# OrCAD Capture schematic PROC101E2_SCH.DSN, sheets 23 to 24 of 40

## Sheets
23 26.FT4232 UART TO USB BRIDGE: size C; title: FT4232 UART TO USB BRIDGE
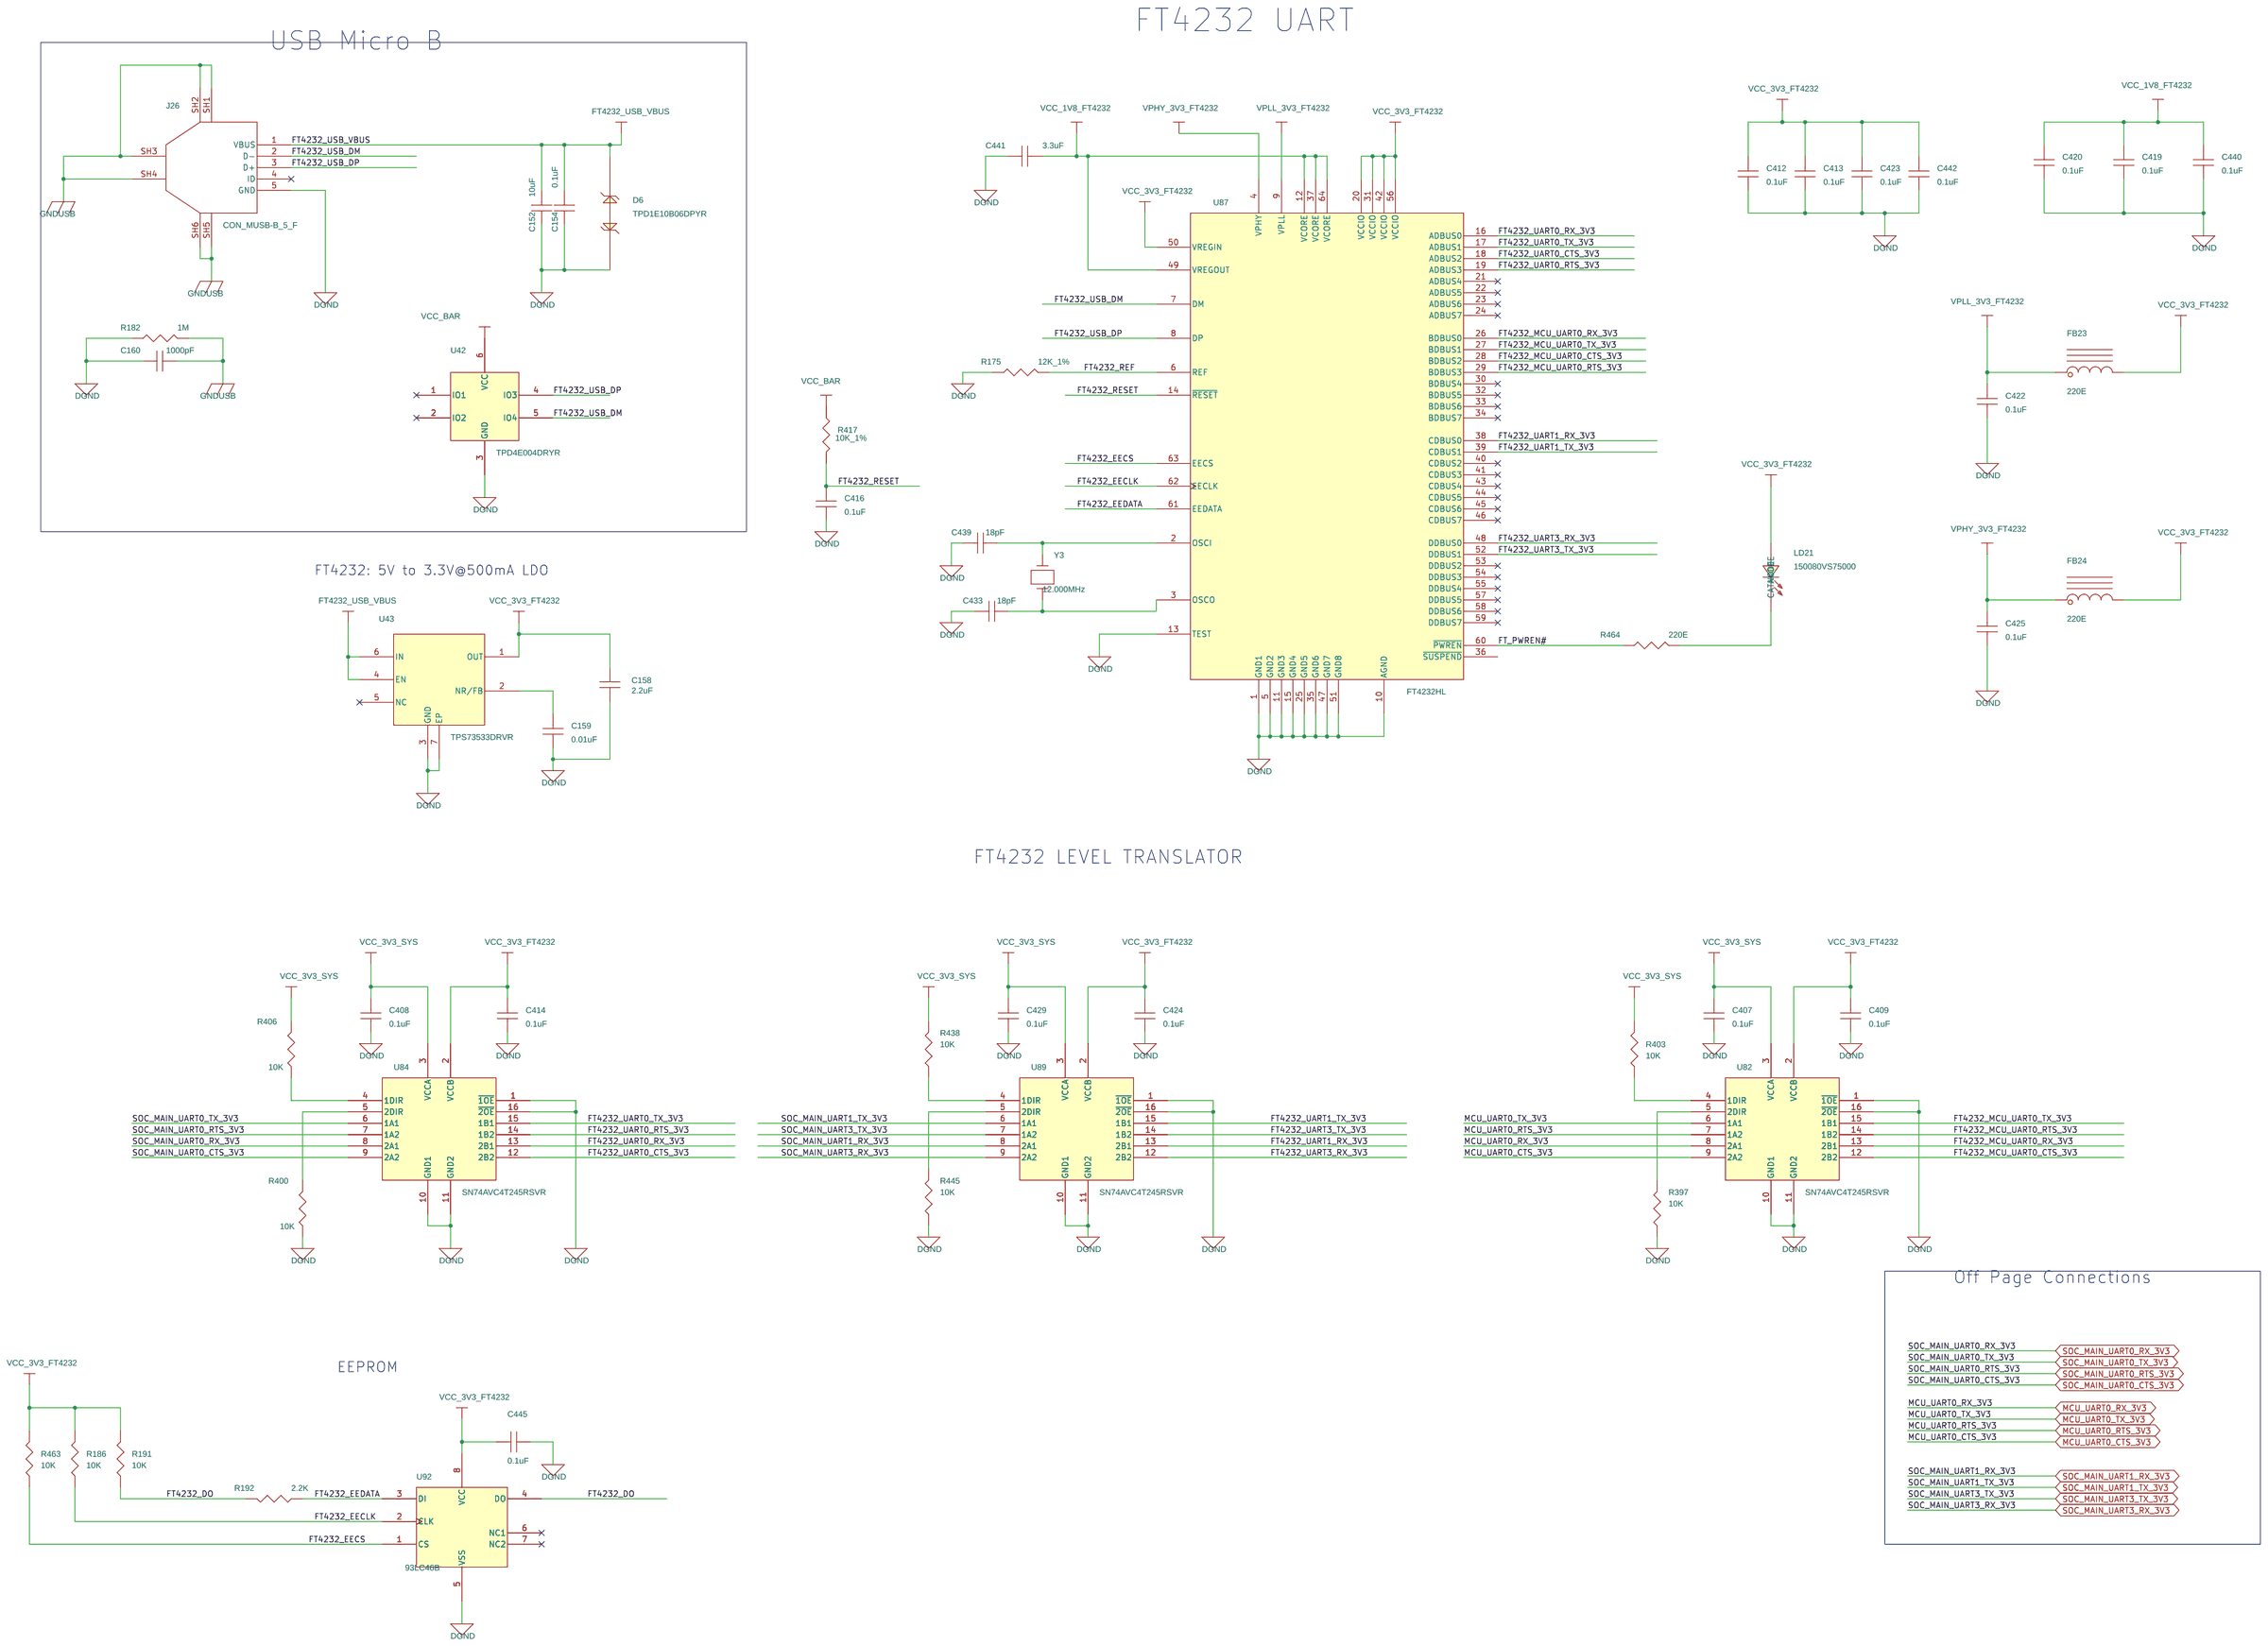
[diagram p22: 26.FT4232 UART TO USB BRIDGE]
24 13.eMMC & SD CARD INTERFACE: size C; title: eMMC FLASH_SDCARD INTERFACE
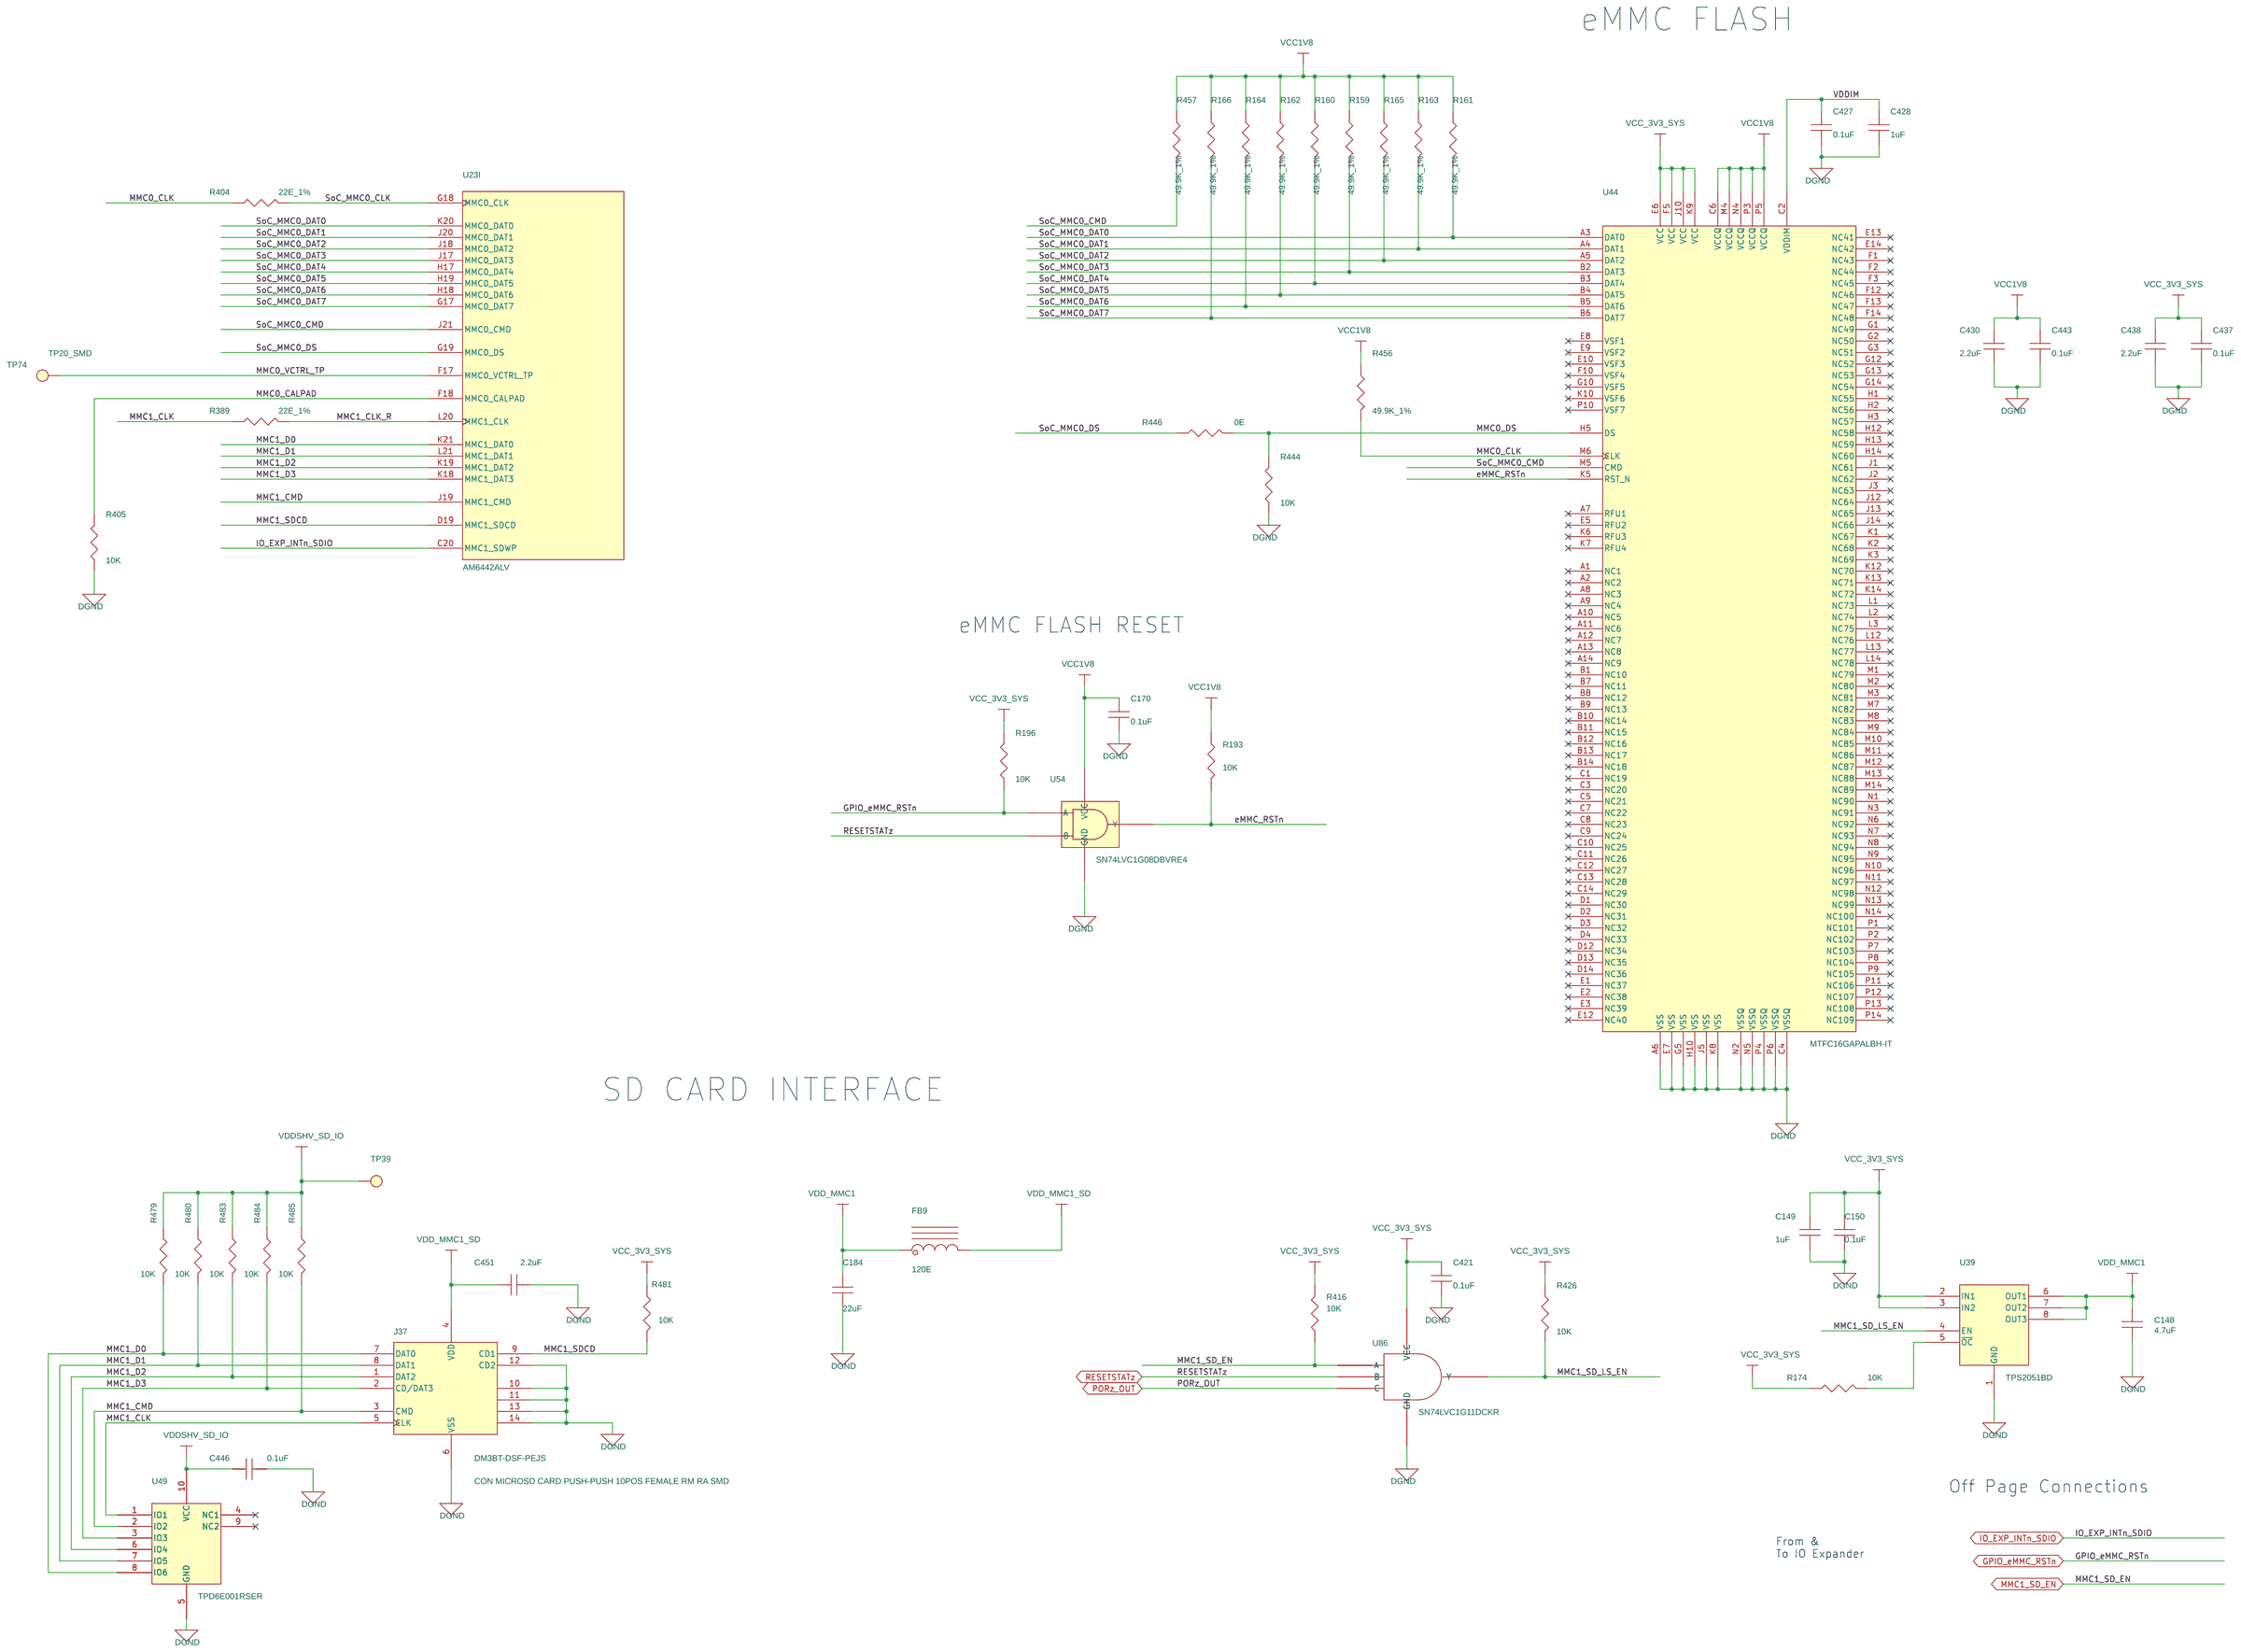
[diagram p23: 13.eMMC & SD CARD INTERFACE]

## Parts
sheet 11.SOC VSS
U23  AM6442ALV  [FCBGA441_31-49_680X680_2-6]  (sections A,B,C,D,E,F,G,H,I,J,K,L,M,N,O,P)
sheet 13.eMMC & SD CARD INTERFACE
C148  4.7uF  [CAP0402_0-75]
C149  1uF  [CAP0402_0-75]
C150  0.1uF  [CAP0402_0-75]
C170  0.1uF  [CAP0402_0-75]
C184  22uF  [CAP0805_1-5]
C421  0.1uF  [CAP0402_0-75]
C427  0.1uF  [CAP0402_0-75]
C428  1uF  [CAP0402_0-75]
C430  2.2uF  [CAP0402_0-75]
C437  0.1uF  [CAP0402_0-75]
C438  2.2uF  [CAP0402_0-75]
C443  0.1uF  [CAP0402_0-75]
C446  0.1uF  [CAP0402_0-75]
C451  2.2uF  [CAP0402_0-75]
FB9  120E  [IND0603_1]
J37  CON_SDCARD10_DM3BT-DSF-PEJS  [CON_SD10_DM3BT-DSF-PEJS_S_R_S_2-4]
R159  49.9K_1%  [RES0402_0-5]
R160  49.9K_1%  [RES0402_0-5]
R161  49.9K_1%  [RES0402_0-5]
R162  49.9K_1%  [RES0402_0-5]
R163  49.9K_1%  [RES0402_0-5]
R164  49.9K_1%  [RES0402_0-5]
R165  49.9K_1%  [RES0402_0-5]
R166  49.9K_1%  [RES0402_0-5]
R174  10K  [RES0402_0-5]
R193  10K  [RES0402_0-5]
R196  10K  [RES0402_0-5]
R389  22E_1%  [RES0402_0-5]
R404  22E_1%  [RES0402_0-5]
R405  10K  [RES0402_0-5]
R416  10K  [RES0402_0-5]
R426  10K  [RES0402_0-5]
R444  10K  [RES0402_0-5]
R446  0E  [RES0402_0-5]
R456  49.9K_1%  [RES0402_0-5]
R457  49.9K_1%  [RES0402_0-5]
R479  10K  [RES0402_0-5]
R480  10K  [RES0402_0-5]
R481  10K  [RES0402_0-5]
R483  10K  [RES0402_0-5]
R484  10K  [RES0402_0-5]
R485  10K  [RES0402_0-5]
TP39  TP20_SMD  [TP20_SMD]
TP74  TP20_SMD  [TP20_SMD]
U39  TPS2051BD  [SOIC8_1-8]
U44  MTFC16GAPALBH-IT  [VFBGA153_19-68_460X520_1-1]
U49  TPD6E001RSER  [UQFN10_19-68_80X60_0-6]
U54  SN74LVC1G08DBVRE4  [SOT23-5]
U86  SN74LVC1G11DCKR  [SC70-6]
sheet 26.FT4232 UART TO USB BRIDGE
C152  10uF  [CAP0402_0-75]
C154  0.1uF  [CAP0402_0-75]
C158  2.2uF  [CAP0402_0-75]
C159  0.01uF  [CAP0402_0-75]
C160  1000pF  [CAP1206_1-75]
C407  0.1uF  [CAP0402_0-75]
C408  0.1uF  [CAP0402_0-75]
C409  0.1uF  [CAP0402_0-75]
C412  0.1uF  [CAP0402_0-75]
C413  0.1uF  [CAP0402_0-75]
C414  0.1uF  [CAP0402_0-75]
C416  0.1uF  [CAP0402_0-75]
C419  0.1uF  [CAP0402_0-75]
C420  0.1uF  [CAP0402_0-75]
C422  0.1uF  [CAP0402_0-75]
C423  0.1uF  [CAP0402_0-75]
C424  0.1uF  [CAP0402_0-75]
C425  0.1uF  [CAP0402_0-75]
C429  0.1uF  [CAP0402_0-75]
C433  18pF  [CAP0402_0-75]
C439  18pF  [CAP0402_0-75]
C440  0.1uF  [CAP0402_0-75]
C441  3.3uF  [CAP0402_0-75]
C442  0.1uF  [CAP0402_0-75]
C445  0.1uF  [CAP0402_0-75]
D6  TPD1E10B06DPYR  [DIO_DFN0402_0-5]
FB23  220E  [IND0402_0-6]
FB24  220E  [IND0402_0-6]
J26  CON_MUSB-B_5_F  [CON_MUSBB5_1051640001_S_R_S_2-5]
LD21  150080VS75000  [LED_150080VS75000_80X50_SMD_0-8]
R175  12K_1%  [RES0402_0-5]
R182  1M  [RES0603_0-75]
R186  10K  [RES0402_0-5]
R191  10K  [RES0402_0-5]
R192  2.2K  [RES0402_0-5]
R397  10K  [RES0402_0-5]
R400  10K  [RES0402_0-5]
R403  10K  [RES0402_0-5]
R406  10K  [RES0402_0-5]
R417  10K_1%  [RES0402_0-5]
R438  10K  [RES0402_0-5]
R445  10K  [RES0402_0-5]
R463  10K  [RES0402_0-5]
R464  220E  [RES0402_0-5]
U42  TPD4E004DRYR  [SON6_19-68_40X60_PB_0-6]
U43  TPS73533DRVR  [SON6_25-59_85X85]
U82  SN74AVC4T245RSVR  [UQFN16_TMUX1574_70X100_0-6]
U84  SN74AVC4T245RSVR  [UQFN16_TMUX1574_70X100_0-6]
U87  FT4232HL  [LQFP64_19-68_390X390_1-6]
U89  SN74AVC4T245RSVR  [UQFN16_TMUX1574_70X100_0-6]
U92  93LC46B  [MSOP8_25-59_125X125_1-1]
Y3  12.000MHz  [XTAL_ABM3_205X130_SMD_1-4]

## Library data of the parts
U23 = AM64-SVB_BGA441: IC AM64 SoC MICROPROCESSOR BGA441; Chkd/date: MANIRAJA/020520; Crtd /date: ALVY/090420; Custom_Duty: 15%; Customs_HS_Code: 85423100; Distributor_name: NA; Distributor_part_number: NA; Footprint Path: Y:\MIS_DATABASE\Library\ALTIUM_TOOL\PCB_FOOTPRINTS\Altium_Footprint_Lib.PcbLib; Height: 2.57MM; Library Path: Y:\MIS_DATABASE\Library\ALTIUM_TOOL\SCHEMATICS_PARTS\MS_MICROPROCESSOR_Library.schlib; Mfr_name: TEXAS INSTRUMENTS; Mfr_part_number: AM6442ASFGGAALV; Mistral Part No: 141220040002; Package: BGA441; Part_type: ICS\DIGITAL\MICROPROCESSOR; Project: AM64x_SVB BRD; RoHS: NA; Temperature: NA; Tolerance: NA; Voltage: NA; Wattage: NA; Weight: NA; Datasheet: Y:\MIS_DATABASE\DATASHEETS\ICS\DIGITAL\MICROCONTROLLER\AM64-SoC_SVB.PDF
C148 = CAP: CAP CERAMIC 4.7uF 10V 20% X5R 0402; Chkd/date: MANIRAJA/230118; Crtd /date: MANIRAJA/230118; Custom_Duty: 15%; Customs_HS_Code: 85322990; Distributor_name: DIGIKEY; Distributor_part_number: 478-10791-1-ND; Footprint Path: Y:\MIS_DATABASE\Library\ALTIUM_TOOL\PCB_FOOTPRINTS\Altium_Footprint_Lib.PcbLib; Height: 0.71MM; Library Path: Y:\MIS_DATABASE\Library\ALTIUM_TOOL\SCHEMATICS_PARTS\MS_DISCRETE_Library.schlib; Mfr_name: AVX CORPORATION; Mfr_part_number: 0402ZD475MAT2A; Mistral Part No: 120012060002-R; Package: 0402; Part_type: CAPACITORS\CERAMIC; Project: TI_MAXIE_CPB; RoHS: RoHS; Temperature: -55°C+85°C; Tolerance: 20%; Voltage: 10V; Wattage: NA; Weight: 0.65mg; Datasheet: Y:\MIS_DATABASE\DATASHEETS\CAPACITORS\AVX_MLC.PDF
C149 C428 = CAP: CAP CERAMIC 1uF 10V 20% X5R 0402; Chkd/date: MANIRAJA/210820; Crtd /date: ALVY/190820; Custom_Duty: 15%; Customs_HS_Code: 85322990; Distributor_name: DIGIKEY; Distributor_part_number: 732-7489-1-ND; Footprint Path: Y:\MIS_DATABASE\Library\ALTIUM_TOOL\PCB_FOOTPRINTS\Altium_Footprint_Lib.PcbLib; Height: 0.55MM; Library Path: Y:\MIS_DATABASE\Library\ALTIUM_TOOL\SCHEMATICS_PARTS\MS_DISCRETE_Library.schlib; Mfr_name: WURTH ELECTRONICS; Mfr_part_number: 885012105012; Mistral Part No: 120020080009-R; Package: 0402; Part_type: CAPACITORS\CERAMIC; Project: AM64x_EVM_BRD; RoHS: RoHS; Temperature: -55°C+85°C; Tolerance: 20%; Voltage: 10V; Wattage: NA; Weight: 0.65mg; Datasheet: Y:\MIS_DATABASE\DATASHEETS\CAPACITORS\885012105012.PDF
C150 C154 C170 C407-C409 C412-C414 C416 C419-C425 C427 C429 C437 C440 C442 C443 C445 C446 = CAP: CAP CERAMIC 0.1uF 25V 20% X5R 0402; Alt_Mfr_name: YAGEO AMERICA; Alt_Mfr_part_number: CC0402KRX5R8BB104; Chkd/date: MANIRAJA/170820; Crtd /date: ALVY/170820; Custom_Duty: 15%; Customs_HS_Code: 85322990; Distributor_name: DIGIKEY; Distributor_part_number: 732-7495-1-ND; Footprint Path: Y:\MIS_DATABASE\Library\ALTIUM_TOOL\PCB_FOOTPRINTS\Altium_Footprint_Lib.PcbLib; Height: 0.55MM; Library Path: Y:\MIS_DATABASE\Library\ALTIUM_TOOL\SCHEMATICS_PARTS\MS_DISCRETE_Library.schlib; Mfr_name: WURTH ELECTRONICS; Mfr_part_number: 885012105018; Mistral Part No: 120020080003-R; Package: 0402; Part_type: CAPACITORS\CERAMIC; Project: AM64x_EVM_BRD; RoHS: RoHS; Temperature: -55°C+85°C; Tolerance: 20%; Voltage: 25V; Wattage: NA; Weight: 0.65mg; Datasheet: Y:\MIS_DATABASE\DATASHEETS\CAPACITORS\885012105018.PDF
C184 = CAP: CAP CERAMIC 22uF 10V 20% X5R 0805; Chkd/date: MANIRAJA/210820; Crtd /date: ALVY/190820; Custom_Duty: 15%; Customs_HS_Code: 85322990; Distributor_name: DIGIKEY; Distributor_part_number: 732-7621-1-ND; Footprint Path: Y:\MIS_DATABASE\Library\ALTIUM_TOOL\PCB_FOOTPRINTS\Altium_Footprint_Lib.PcbLib; Height: 1.45MM; Library Path: Y:\MIS_DATABASE\Library\ALTIUM_TOOL\SCHEMATICS_PARTS\MS_DISCRETE_Library.schlib; Mfr_name: WURTH ELECTRONICS; Mfr_part_number: 885012107011; Mistral Part No: 120020080010-R; Package: 0805; Part_type: CAPACITORS\CERAMIC; Project: AM64x_EVM_BRD; RoHS: RoHS; Temperature: -55°C+85°C; Tolerance: 20%; Voltage: 10V; Wattage: NA; Weight: 5.5mg; Datasheet: Y:\MIS_DATABASE\DATASHEETS\CAPACITORS\885012107011.PDF
C158 C430 C438 C451 = CAP: CAP CERAMIC 2.2uF 10V 20% X5R 0402; Chkd/date: MANIRAJA/170820; Crtd /date: ALVY/170820; Custom_Duty: 15%; Customs_HS_Code: 85322990; Distributor_name: DIGIKEY; Distributor_part_number: 732-7490-1-ND; Footprint Path: Y:\MIS_DATABASE\Library\ALTIUM_TOOL\PCB_FOOTPRINTS\Altium_Footprint_Lib.PcbLib; Height: 0.55MM; Library Path: Y:\MIS_DATABASE\Library\ALTIUM_TOOL\SCHEMATICS_PARTS\MS_DISCRETE_Library.schlib; Mfr_name: WURTH ELECTRONICS; Mfr_part_number: 885012105013; Mistral Part No: 120019040036-R; Package: 0402; Part_type: CAPACITORS\CERAMIC; Project: AM64x_EVM_BRD; RoHS: RoHS; Temperature: -55°C+85°C; Tolerance: 20%; Voltage: 10V; Wattage: NA; Weight: 0.65mg; Datasheet: Y:\MIS_DATABASE\DATASHEETS\CAPACITORS\885012105013.PDF
FB9 = INDUCTOR_FERRITE: IND FERRITE BEAD CHIP 120E 2A 0603; Chkd/date: MANIRAJA/180820; Crtd /date: ALVY/180820; Custom_Duty: 24%; Customs_HS_Code: 85437099; Distributor_name: DIGIKEY; Distributor_part_number: 732-782631141CT-ND; Footprint Path: Y:\MIS_DATABASE\Library\ALTIUM_TOOL\PCB_FOOTPRINTS\Altium_Footprint_Lib.PcbLib; Height: 1.00MM; Library Path: Y:\MIS_DATABASE\Library\ALTIUM_TOOL\SCHEMATICS_PARTS\MS_FILTER_Library.schlib; Mfr_name: WURTH ELECTRONICS; Mfr_part_number: 782631141; Mistral Part No: 130020080015-R; Package: 0603; Part_type: INDUCTOR; Project: AM64x_EVM_BRD; RoHS: RoHS; Temperature: -55°C+125°C; Tolerance: 25%; Voltage: NA; Wattage: NA; Weight: NA; Datasheet: Y:\MIS_DATABASE\DATASHEETS\DISCRETES\INDUCTORS\782631141.PDF
J37 = CON_SDCARD_10_DM3BT-DSF-PEJS: CON MICROSD CARD PUSH-PUSH 10POS FEMALE RM RA SMD; Chkd/date: MANIRAJA/080218; Crtd /date: BAVISH/190111; Custom_Duty: 24%; Customs_HS_Code: 85369090; Distributor_name: DIGIKEY; Distributor_part_number: HR1942CT-ND; Footprint Path: Y:\MIS_DATABASE\Library\ALTIUM_TOOL\PCB_FOOTPRINTS\Altium_Footprint_Lib.PcbLib; Height: 2.38MM; Library Path: Y:\MIS_DATABASE\Library\ALTIUM_TOOL\SCHEMATICS_PARTS\MS_CONNECTOR_Library.schlib; Mfr_name: HIROSE ELECTRIC; Mfr_part_number: DM3BT-DSF-PEJS; Mistral Part No: 150011010020-R; Package: SMD; Part_type: CONNECTOR\MEMORY CARD; Project: EBOOK; RoHS: RoHS; Temperature: -25°C+85°C; Tolerance: NA; Voltage: NA; Wattage: NA; Weight: 1.315g; Datasheet: Y:\MIS_DATABASE\DATASHEETS\CONNECTORS\DM3-SERIES.PDF
R159-R166 R457 = RESISTOR: RES 49.9K 1/16W 1% 0402; Assembly: DNI; Chkd/date: MAZHAR/220709; Crtd /date: GEETHA/090606; Custom_Duty: 15%; Customs_HS_Code: 85332119; Distributor_name: DIGIKEY; Distributor_part_number: 311-49.9KLRCT-ND; Footprint Path: Y:\MIS_DATABASE\Library\ALTIUM_TOOL\PCB_FOOTPRINTS\Altium_Footprint_Lib.PcbLib; Height: 0.40MM; Library Path: Y:\MIS_DATABASE\Library\ALTIUM_TOOL\SCHEMATICS_PARTS\MS_DISCRETE_Library.schlib; Mfr_name: YAGEO AMERICA; Mfr_part_number: RC0402FR-0749K9L; Mistral Part No: 110009030902-R; Package: 0402; Part_type: RESISTORS\FIXED; Project: PNAV; RoHS: RoHS; Temperature: -55°C+155°C; Tolerance: 1%; Voltage: NA; Wattage: 1/16W; Weight: 0.65mg; Datasheet: Y:\MIS_DATABASE\DATASHEETS\RESISTORS\RCXXXXL-SER_MAR18.PDF
R174 R186 R191 R196 R397 R400 R403 R405 R406 R416 R438 R444 R445 R463 R481 = RESISTOR: RES 10K 1/16W 5% 0402; Chkd/date: VASANTHA/061216; Crtd /date: MAZHAR/230805; Custom_Duty: 15%; Customs_HS_Code: 85332119; Distributor_name: DIGIKEY; Distributor_part_number: 311-10KJRCT-ND; Footprint Path: Y:\MIS_DATABASE\Library\ALTIUM_TOOL\PCB_FOOTPRINTS\Altium_Footprint_Lib.PcbLib; Height: 0.40MM; Library Path: Y:\MIS_DATABASE\Library\ALTIUM_TOOL\SCHEMATICS_PARTS\MS_DISCRETE_Library.schlib; Mfr_name: YAGEO AMERICA; Mfr_part_number: RC0402JR-0710KL; Mistral Part No: 110011060021-R; Package: 0402; Part_type: RESISTORS\FIXED; Project: HSE; RoHS: RoHS; Temperature: -55°C+155°C; Tolerance: 5%; Voltage: NA; Wattage: 1/16W; Weight: 0.65mg; Datasheet: Y:\MIS_DATABASE\DATASHEETS\RESISTORS\RCXXXXL-SER_MAR18.PDF
R193 R426 R479 R480 R483-R485 = RESISTOR: RES 10K 1/16W 5% 0402; Assembly: DNI; Chkd/date: VASANTHA/061216; Crtd /date: MAZHAR/230805; Custom_Duty: 15%; Customs_HS_Code: 85332119; Distributor_name: DIGIKEY; Distributor_part_number: 311-10KJRCT-ND; Footprint Path: Y:\MIS_DATABASE\Library\ALTIUM_TOOL\PCB_FOOTPRINTS\Altium_Footprint_Lib.PcbLib; Height: 0.40MM; Library Path: Y:\MIS_DATABASE\Library\ALTIUM_TOOL\SCHEMATICS_PARTS\MS_DISCRETE_Library.schlib; Mfr_name: YAGEO AMERICA; Mfr_part_number: RC0402JR-0710KL; Mistral Part No: 110011060021-R; Package: 0402; Part_type: RESISTORS\FIXED; Project: HSE; RoHS: RoHS; Temperature: -55°C+155°C; Tolerance: 5%; Voltage: NA; Wattage: 1/16W; Weight: 0.65mg; Datasheet: Y:\MIS_DATABASE\DATASHEETS\RESISTORS\RCXXXXL-SER_MAR18.PDF
R389 = RESISTOR: RES 22E 1/16W 1% 0402; Chkd/date: SUHAS/290910; Crtd /date: MAZHAR/090909; Cust_part_number: 4700-80047E; Custom_Duty: 15%; Customs_HS_Code: 85332119; Distributor_name: DIGIKEY; Distributor_part_number: 311-22.0LRCT-ND; Footprint Path: Y:\MIS_DATABASE\Library\ALTIUM_TOOL\PCB_FOOTPRINTS\Altium_Footprint_Lib.PcbLib; Height: 0.40MM; Library Path: Y:\MIS_DATABASE\Library\ALTIUM_TOOL\SCHEMATICS_PARTS\MS_DISCRETE_Library.schlib; Mfr_name: YAGEO AMERICA; Mfr_part_number: RC0402FR-0722RL; Mistral Part No: 110009090004-R; Package: 0402; Part_type: RESISTORS\FIXED; Project: VMEFMCD; RoHS: RoHS; Temperature: -55°C+155°C; Tolerance: 1%; Voltage: NA; Wattage: 1/16W; Weight: 0.65mg; Datasheet: Y:\MIS_DATABASE\DATASHEETS\RESISTORS\RCXXXXL-SER_MAR18.PDF
R404 = RESISTOR: RES 22E 1/16W 1% 0402; Chkd/date: SUHAS/290910; Crtd /date: MAZHAR/090909; Cust_part_number: 4700-80047E; Custom_Duty: 15%; Customs_HS_Code: 85332119; Distributor_name: DIGIKEY; Distributor_part_number: 311-22.0LRCT-ND; Footprint Path: Y:\MIS_DATABASE\Library\ALTIUM_TOOL\PCB_FOOTPRINTS\Altium_Footprint_Lib.PcbLib; Height: 0.40MM; Library Path: Y:\MIS_DATABASE\Library\ALTIUM_TOOL\SCHEMATICS_PARTS\MS_DISCRETE_Library.schlib; Mfr_name: YAGEO AMERICA; Mfr_part_number: RC0402FR-0722RL; Mistral Part No: 110009090004-R; Package: 0402; Part_type: RESISTORS\FIXED; Project: VMEFMCD; RoHS: RoHS; SIGNAL_MODEL: RESISTOR_RES0402_22E_22E; Temperature: -55°C+155°C; Tolerance: 1%; Voltage: NA; Wattage: 1/16W; Weight: 0.65mg; Datasheet: Y:\MIS_DATABASE\DATASHEETS\RESISTORS\RCXXXXL-SER_MAR18.PDF
R446 = RESISTOR: RES 0E 1/16W JUMPER 0402; Chkd/date: VASANTHA/201216; Crtd /date: MUDDU/190810; Custom_Duty: 15%; Customs_HS_Code: 85332119; Distributor_name: DIGIKEY; Distributor_part_number: 541-0.0JCT-ND; Footprint Path: Y:\MIS_DATABASE\Library\ALTIUM_TOOL\PCB_FOOTPRINTS\Altium_Footprint_Lib.PcbLib; Height: 0.40MM; Library Path: Y:\MIS_DATABASE\Library\ALTIUM_TOOL\SCHEMATICS_PARTS\MS_DISCRETE_Library.schlib; Mfr_name: VISHAY; Mfr_part_number: CRCW04020000Z0ED; Mistral Part No: 110010080019-R; Package: 0402; Part_type: RESISTORS\FIXED; Project: PB_BUGBASE; RoHS: RoHS; Temperature: -55°C+155°C; Tolerance: NA; Voltage: NA; Wattage: 1/16W; Weight: 0.65mg; Datasheet: Y:\MIS_DATABASE\DATASHEETS\RESISTORS\CRCW0603.PDF
R456 = RESISTOR: RES 49.9K 1/16W 1% 0402; Chkd/date: MAZHAR/220709; Crtd /date: GEETHA/090606; Custom_Duty: 15%; Customs_HS_Code: 85332119; Distributor_name: DIGIKEY; Distributor_part_number: 311-49.9KLRCT-ND; Footprint Path: Y:\MIS_DATABASE\Library\ALTIUM_TOOL\PCB_FOOTPRINTS\Altium_Footprint_Lib.PcbLib; Height: 0.40MM; Library Path: Y:\MIS_DATABASE\Library\ALTIUM_TOOL\SCHEMATICS_PARTS\MS_DISCRETE_Library.schlib; Mfr_name: YAGEO AMERICA; Mfr_part_number: RC0402FR-0749K9L; Mistral Part No: 110009030902-R; Package: 0402; Part_type: RESISTORS\FIXED; Project: PNAV; RoHS: RoHS; Temperature: -55°C+155°C; Tolerance: 1%; Voltage: NA; Wattage: 1/16W; Weight: 0.65mg; Datasheet: Y:\MIS_DATABASE\DATASHEETS\RESISTORS\RCXXXXL-SER_MAR18.PDF
TP39 TP74 = TESTPOINT: TESTPOINT CIR 20 SMD; Chkd/date: SHREESHAIL/171006; Crtd /date: MAZHAR/171006; Custom_Duty: NA; Customs_HS_Code: NA; Distributor_name: NA; Distributor_part_number: NA; Footprint Path: Y:\MIS_DATABASE\Library\ALTIUM_TOOL\PCB_FOOTPRINTS\Altium_Footprint_Lib.PcbLib; Height: NA; Library Path: Y:\MIS_DATABASE\Library\ALTIUM_TOOL\SCHEMATICS_PARTS\MS_DISCRETE_Library.schlib; MECHANICAL 3D STEP FILE: NA; Mfr_name: LOCAL; Mistral Part No: NA; Package: SMD; Project: BT MODULE_CSRBC04; RoHS: NA; Temperature: NA; Tolerance: NA; Voltage: NA; Wattage: NA; Weight: NA; Datasheet: NA
U39 = TPS2051BD_SOIC8: IC POWER DISTRIBUTION SWITCH SOIC8; Chkd/date: NAVEED/150714; Crtd /date: VASANTHA/190614; Custom_Duty: 15%; Customs_HS_Code: 85423100; Distributor_name: DIGIKEY; Distributor_part_number: 296-26911-5-ND; Footprint Path: Y:\MIS_DATABASE\Library\ALTIUM_TOOL\PCB_FOOTPRINTS\Altium_Footprint_Lib.PcbLib; Height: 1.75MM; Library Path: Y:\MIS_DATABASE\Library\ALTIUM_TOOL\SCHEMATICS_PARTS\MS_MISCPOWER_Library.schlib; Mfr_name: TEXAS INSTRUMENTS; Mistral Part No: 142014060011-R; Package: SOIC8; Part_type: ICS\POWER; Project: AEGIS_POM; RoHS: RoHS; Temperature: -40°C+125°C; Tolerance: NA; Voltage: NA; Wattage: NA; Weight: 72.6mg; Datasheet: Y:\MIS_DATABASE\DATASHEETS\MISC\REGULATORS\TPS2051BDBVR.PDF
U44 = MTFC16GAPALBH_TFBGA153: IC 16GB e-MMC MEMORY TFBGA153; Chkd/date: MANIRAJA/070220; Crtd /date: ALVY/070220; Custom_Duty: 15%; Customs_HS_Code: 85423100; Distributor_name: DIGIKEY; Distributor_part_number: MTFC16GAPALBH-IT-ND; Footprint Path: Y:\MIS_DATABASE\Library\ALTIUM_TOOL\PCB_FOOTPRINTS\Altium_Footprint_Lib.PcbLib; Height: 1.10MM; Library Path: Y:\MIS_DATABASE\Library\ALTIUM_TOOL\SCHEMATICS_PARTS\MS_MISCMEMORY_Library.schlib; Mfr_name: MICRON; Mistral Part No: 141120020001-R; Package: TFBGA153; Part_type: ICS\DIGITAL\MEMORY; Project: TI_MAXIE_CPB; RoHS: RoHS; Temperature: -40°C+85°C; Tolerance: NA; Voltage: NA; Wattage: NA; Weight: NA; Datasheet: Y:\MIS_DATABASE\DATASHEETS\ICS\MEMORY\MTFCXX-IT.PDF
U49 = TPD6E001RSE_UQFN10: IC 6CH ESD-PROTECTION ARRAY UQFN10; Chkd/date: USMAN/070612; Crtd /date: BAVISH/160811; Custom_Duty: 15%; Customs_HS_Code: 85423100; Distributor_name: DIGIKEY; Distributor_part_number: 296-21888-1-ND; Footprint Path: Y:\MIS_DATABASE\Library\ALTIUM_TOOL\PCB_FOOTPRINTS\Altium_Footprint_Lib.PcbLib; Height: 0.60MM; IBISSP_MODLES: Y:\MIS_DATABASE\IBIS\ICs\INTERFACE\TPD6E001RSE.IBS; Library Path: Y:\MIS_DATABASE\Library\ALTIUM_TOOL\SCHEMATICS_PARTS\MS_MISCINTERFACE_Library.schlib; Mfr_name: TEXAS INSTRUMENTS; Mistral Part No: 141011080020-R; Package: UQFN10; Part_type: ICS\INTERFACE; Project: DM385EVM_BASE-BOARD; RoHS: RoHS; Temperature: -40°C+85°C; Tolerance: NA; Voltage: NA; Wattage: NA; Weight: 7mg; Datasheet: Y:\MIS_DATABASE\DATASHEETS\ICS\INTERFACE\TPD6E001.PDF
U54 = SN74LVC1G08DBVRE4_SOT23-5: IC SINGLE 2-INPUT POSITIVE AND GATE SOT23-5; Chkd/date: SUHAS/221010; Crtd /date: USMAN/151008; Custom_Duty: 15%; Customs_HS_Code: 85423100; Distributor_name: DIGIKEY; Distributor_part_number: SN74LVC1G08DBVRE4-ND; Height: 1.45MM; Mfr_name: TEXAS INSTRUMENTS; Mistral Part No: 141009060026-R; Part_type: ICS\DIGITAL\GATES; Project: KHAN_MAIN; RoHS: Sb/ Br FREE; Temperature: -40°C+85°C; Datasheet: Y:\MIS_DATABASE\DATASHEETS\ICS\DIGITAL\GATES\SN74LVC1G08.PDF
U86 = SN74LVC1G11DCKR_SC70-6: IC SINGLE 3-INPUT POSITIVE-AND GATE SC70-6; Chkd/date: SHREESHAIL/220506; Crtd /date: MAZHAR/150506; Custom_Duty: 15%; Customs_HS_Code: 85423100; Distributor_name: DIGIKEY; Distributor_part_number: 296-18066-1-ND; Height: 1.10MM; Mfr_name: TEXAS INSTRUMENTS; Mistral Part No: 141009030230-R; Part_type: ICS\DIGITAL\GATES; Project: VOCERA; RoHS: Sb/ Br FREE; Datasheet: Y:\MIS_DATABASE\DATASHEETS\ICS\DIGITAL\GATES\SN74LVC1G.PDF
C152 = CAP: CAP CERAMIC 10uF 10V 20% X5R 0402; Chkd/date: MANIRAJA/300520; Crtd /date: ALVY/260520; Custom_Duty: 15%; Customs_HS_Code: 85322990; Distributor_name: DIGIKEY; Distributor_part_number: 490-GRM155R61A106ME11DTR-ND; Footprint Path: Y:\MIS_DATABASE\Library\ALTIUM_TOOL\PCB_FOOTPRINTS\Altium_Footprint_Lib.PcbLib; Height: 0.55MM; Library Path: Y:\MIS_DATABASE\Library\ALTIUM_TOOL\SCHEMATICS_PARTS\MS_DISCRETE_Library.schlib; Mfr_name: MURATA; Mfr_part_number: GRM155R61A106ME11D; Mistral Part No: 120013110019-R; Package: 0402; Part_type: CAPACITORS\CERAMIC; Project: QCS610_NANOSOM; RoHS: RoHS; Temperature: -55°C+85°C; Tolerance: 20%; Voltage: 10V; Wattage: NA; Weight: 3.1mg; Datasheet: Y:\MIS_DATABASE\DATASHEETS\CAPACITORS\MURATA-GXX-SER_NOV17.PDF
C159 = CAP: CAP CERAMIC 0.01uF 25V 10% X7R 0402; Chkd/date: MANIRAJA/170820; Crtd /date: ALVY/170820; Custom_Duty: 15%; Customs_HS_Code: 85322990; Distributor_name: DIGIKEY; Distributor_part_number: 732-7545-1-ND; Footprint Path: Y:\MIS_DATABASE\Library\ALTIUM_TOOL\PCB_FOOTPRINTS\Altium_Footprint_Lib.PcbLib; Height: 0.55MM; Library Path: Y:\MIS_DATABASE\Library\ALTIUM_TOOL\SCHEMATICS_PARTS\MS_DISCRETE_Library.schlib; Mfr_name: WURTH ELECTRONICS; Mfr_part_number: 885012205050; Mistral Part No: 120011090040-R; Package: 0402; Part_type: CAPACITORS\CERAMIC; Project: AM64x_EVM_BRD; RoHS: RoHS; Temperature: -55°C+125°C; Tolerance: 10%; Voltage: 25V; Wattage: NA; Weight: 0.65mg; Datasheet: Y:\MIS_DATABASE\DATASHEETS\CAPACITORS\885012205050.PDF
C160 = CAP: CAP CERAMIC 1000pF 2KV 10% X7R 1206; Chkd/date: SHREESHAIL/291106; Crtd /date: MAZHAR/281106; Custom_Duty: 15%; Customs_HS_Code: 85322990; Distributor_name: DIGIKEY; Distributor_part_number: 478-2956-1-ND; Footprint Path: Y:\MIS_DATABASE\Library\ALTIUM_TOOL\PCB_FOOTPRINTS\Altium_Footprint_Lib.PcbLib; Height: 1.52MM; Library Path: Y:\MIS_DATABASE\Library\ALTIUM_TOOL\SCHEMATICS_PARTS\MS_DISCRETE_Library.schlib; Mfr_name: AVX CORPORATION; Mfr_part_number: 1206GC102KAT1A; Mistral Part No: 120015080006-R; Package: 1206; Part_type: CAPACITORS\CERAMIC; Project: ADR1B; RoHS: RoHS; Temperature: -55°C+125°C; Tolerance: 10%; Voltage: 2KV; Wattage: NA; Weight: 16.2mg; Datasheet: Y:\MIS_DATABASE\DATASHEETS\CAPACITORS\AVX_HV-MLC.PDF
C433 C439 = CAP: CAP CERAMIC 18pF 50V 5% C0G(NP0) 0402; Chkd/date: MANIRAJA/070220; Crtd /date: ALVY/070220; Custom_Duty: 15%; Customs_HS_Code: 85322990; Distributor_name: DIGIKEY; Distributor_part_number: 399-8952-1-ND; Footprint Path: Y:\MIS_DATABASE\Library\ALTIUM_TOOL\PCB_FOOTPRINTS\Altium_Footprint_Lib.PcbLib; Height: 0.55MM; Library Path: Y:\MIS_DATABASE\Library\ALTIUM_TOOL\SCHEMATICS_PARTS\MS_DISCRETE_Library.schlib; Mfr_name: KEMET; Mfr_part_number: C0402C180J5GAC7867; Mistral Part No: 120011090034-R; Package: 0402; Part_type: CAPACITORS\CERAMIC; Project: TI_MAXIE_CPB; RoHS: RoHS; Temperature: -55°C+125°C; Tolerance: 5%; Voltage: 50V; Wattage: NA; Weight: 0.65mg; Datasheet: Y:\MIS_DATABASE\DATASHEETS\CAPACITORS\KEMET-C0G_SERIES.PDF
C441 = CAP: CAP CERAMIC 3.3uF 10V 10% X5R 0402; Chkd/date: ALVY/190320; Crtd /date: ALVY/190320; Custom_Duty: 15%; Customs_HS_Code: 85322990; Distributor_name: DIGIKEY; Distributor_part_number: 445-13819-1-ND; Footprint Path: Y:\MIS_DATABASE\Library\ALTIUM_TOOL\PCB_FOOTPRINTS\Altium_Footprint_Lib.PcbLib; Height: 0.60MM; Library Path: Y:\MIS_DATABASE\Library\ALTIUM_TOOL\SCHEMATICS_PARTS\MS_DISCRETE_Library.schlib; Mfr_name: TDK CORPORATION; Mfr_part_number: C1005X5R1A335K050BC; Mistral Part No: 120020030002-R; Package: 0402; Part_type: CAPACITORS\CERAMIC; Project: 32CHSCC_V3_PREAMP-CA; RoHS: RoHS; Temperature: -55°C+85°C; Tolerance: 10%; Voltage: 10V; Wattage: NA; Weight: 34mg; Datasheet: Y:\MIS_DATABASE\DATASHEETS\CAPACITORS\TDK-C-SER_JUL17.PDF
D6 = DIODE_SOD323: DIODE 1CH ESD PROTECTION X1SON2; Chkd/date: MANIRAJA/040420; Crtd /date: VASANTHA/181114; Custom_Duty: 15%; Customs_HS_Code: 85423100; Distributor_name: DIGIKEY; Distributor_part_number: 296-30406-1-ND; Footprint Path: Y:\MIS_DATABASE\Library\ALTIUM_TOOL\PCB_FOOTPRINTS\Altium_Footprint_Lib.PcbLib; Height: 0.45MM; Library Path: Y:\MIS_DATABASE\Library\ALTIUM_TOOL\SCHEMATICS_PARTS\MS_DISCRETE_Library.schlib; Mfr_name: TEXAS INSTRUMENTS; Mistral Part No: 130014110022-R; Package: X1SON2; Part_type: DIODE; Project: GALILEO_EVM; RoHS: RoHS; Temperature: -40°C+125°C; Tolerance: NA; Voltage: NA; Wattage: NA; Weight: 1mg; Datasheet: Y:\MIS_DATABASE\DATASHEETS\ICS\INTERFACE\TPD1E10B06-SER.PDF
FB23 FB24 = INDUCTOR_FERRITE: IND FERRITE BEAD CHIP 220E 300mA 0402; Chkd/date: MANIRAJA/180820; Crtd /date: ALVY/180820; Custom_Duty: 24%; Customs_HS_Code: 85437099; Distributor_name: DIGIKEY; Distributor_part_number: 732-1569-1-ND; Footprint Path: Y:\MIS_DATABASE\Library\ALTIUM_TOOL\PCB_FOOTPRINTS\Altium_Footprint_Lib.PcbLib; Height: 0.55MM; Library Path: Y:\MIS_DATABASE\Library\ALTIUM_TOOL\SCHEMATICS_PARTS\MS_FILTER_Library.schlib; Mfr_name: WURTH ELECTRONICS; Mfr_part_number: 742792780; Mistral Part No: 130020080018-R; Package: 0402; Part_type: INDUCTOR; Project: AM64x_EVM_BRD; RoHS: RoHS; Temperature: -55°C+125°C; Tolerance: 25%; Voltage: NA; Wattage: NA; Weight: 0.65mg; Datasheet: Y:\MIS_DATABASE\DATASHEETS\DISCRETES\INDUCTORS\742792780.PDF
J26 = CON_MUSB-B_5_1051640001: CON MICRO USB-B TYPE 5POS FEMALE RT SMD; Chkd/date: MANIRAJA/230817; Crtd /date: MANIRAJA/230817; Custom_Duty: 24%; Customs_HS_Code: 85369090; Distributor_name: DIGIKEY; Distributor_part_number: WM11263CT-ND; Height: 2.45MM; Mfr_name: MOLEX; Mfr_part_number: 1051640001; Mistral Part No: 150017080018-R; Package: SMD; Part_type: CONNECTOR\USB; Project: TI_MAXIE_CPB; RoHS: RoHS; Temperature: -35°C+85°C; Tolerance: NA; Voltage: NA; Wattage: NA; Weight: 234mg; Datasheet: Y:\MIS_DATABASE\DATASHEETS\CONNECTORS\1051640001.PDF
LD21 = DIODE_LED: DIODE LED BRIGHT GREEN SMD; Chkd/date: MANIRAJA/180820; Crtd /date: ALVY/180820; Custom_Duty: 24%; Customs_HS_Code: 85439000; Distributor_name: DIGIKEY; Distributor_part_number: 732-4986-1-ND; Footprint Path: Y:\MIS_DATABASE\Library\ALTIUM_TOOL\PCB_FOOTPRINTS\Altium_Footprint_Lib.PcbLib; Height: 0.80MM; Library Path: Y:\MIS_DATABASE\Library\ALTIUM_TOOL\SCHEMATICS_PARTS\MS_OPTO_Library.schlib; Mfr_name: WURTH ELECTRONICS; Mistral Part No: 130020080012-R; Package: SMD; Part_type: OPTO\LED; Project: AM64x_EVM_BRD; RoHS: RoHS; Temperature: -40°C+85°C; Tolerance: NA; Voltage: NA; Wattage: NA; Weight: 10mg; Datasheet: Y:\MIS_DATABASE\DATASHEETS\DISCRETES\LEDS\150080VS75000.PDF
R175 = RESISTOR: RES 12K 1/10W 1% 0402; Chkd/date: VASANTHA/041215; Crtd /date: VASANTHA/041215; Custom_Duty: 15%; Customs_HS_Code: 85332119; Distributor_name: DIGIKEY; Distributor_part_number: P12.0KLCT-ND; Footprint Path: Y:\MIS_DATABASE\Library\ALTIUM_TOOL\PCB_FOOTPRINTS\Altium_Footprint_Lib.PcbLib; Height: 0.40MM; Library Path: Y:\MIS_DATABASE\Library\ALTIUM_TOOL\SCHEMATICS_PARTS\MS_DISCRETE_Library.schlib; Mfr_name: PANASONIC-ECG; Mfr_part_number: ERJ-2RKF1202X; Mistral Part No: 110019040053-R; Package: 0402; Part_type: RESISTORS\FIXED; Project: TI_C5545; RoHS: RoHS; Temperature: -55°C+155°C; Tolerance: 1%; Voltage: NA; Wattage: 1/10W; Weight: 0.8mg; Datasheet: Y:\MIS_DATABASE\DATASHEETS\RESISTORS\PAN-ERJSER_NOV17.PDF
R182 = RESISTOR: RES 1M 1/10W 5% 0603; Chkd/date: VASANTHA/060217; Crtd /date: USMAN/111207; Custom_Duty: 15%; Customs_HS_Code: 85332119; Distributor_name: DIGIKEY; Distributor_part_number: P1.0MGCT-ND; Footprint Path: Y:\MIS_DATABASE\Library\ALTIUM_TOOL\PCB_FOOTPRINTS\Altium_Footprint_Lib.PcbLib; Height: 0.55MM; Library Path: Y:\MIS_DATABASE\Library\ALTIUM_TOOL\SCHEMATICS_PARTS\MS_DISCRETE_Library.schlib; Mfr_name: PANASONIC-ECG; Mfr_part_number: ERJ-3GEYJ105V; Mistral Part No: 110009030413-R; Package: 0603; Part_type: RESISTORS\FIXED; Project: BSN; RoHS: RoHS; Temperature: -55°C+155°C; Tolerance: 5%; Voltage: NA; Wattage: 1/10W; Weight: 2mg; Datasheet: Y:\MIS_DATABASE\DATASHEETS\RESISTORS\PAN-ERJSER_NOV17.PDF
R192 = RESISTOR: RES 2.2K 1/16W 5% 0402; Chkd/date: VASANTHA/061216; Crtd /date: BAVISH/021210; Custom_Duty: 15%; Customs_HS_Code: 85332119; Distributor_name: DIGIKEY; Distributor_part_number: 311-2.2KJRCT-ND; Footprint Path: Y:\MIS_DATABASE\Library\ALTIUM_TOOL\PCB_FOOTPRINTS\Altium_Footprint_Lib.PcbLib; Height: 0.40MM; Library Path: Y:\MIS_DATABASE\Library\ALTIUM_TOOL\SCHEMATICS_PARTS\MS_DISCRETE_Library.schlib; Mfr_name: YAGEO AMERICA; Mfr_part_number: RC0402JR-072K2L; Mistral Part No: 110010120018-R; Package: 0402; Part_type: RESISTORS\FIXED; Project: TE4; RoHS: RoHS; Temperature: -55°C+155°C; Tolerance: 5%; Voltage: NA; Wattage: 1/16W; Weight: 0.65mg; Datasheet: Y:\MIS_DATABASE\DATASHEETS\RESISTORS\RCXXXXL-SER_MAR18.PDF
R417 = RESISTOR: RES 10K 1/16W 1% 0402; Chkd/date: VASANTHA/201216; Crtd /date: GEETHA/290506; Custom_Duty: 15%; Customs_HS_Code: 85332119; Distributor_name: DIGIKEY; Distributor_part_number: 311-10.0KLRTR-ND; Footprint Path: Y:\MIS_DATABASE\Library\ALTIUM_TOOL\PCB_FOOTPRINTS\Altium_Footprint_Lib.PcbLib; Height: 0.40MM; Library Path: Y:\MIS_DATABASE\Library\ALTIUM_TOOL\SCHEMATICS_PARTS\MS_DISCRETE_Library.schlib; Mfr_name: YAGEO AMERICA; Mfr_part_number: RC0402FR-0710KL; Mistral Part No: 110015090015-R; Package: 0402; Part_type: RESISTORS\FIXED; Project: VOCERA; RoHS: RoHS; Temperature: -55°C+155°C; Tolerance: 1%; Voltage: NA; Wattage: 1/16W; Weight: 0.65mg; Datasheet: Y:\MIS_DATABASE\DATASHEETS\RESISTORS\RCXXXXL-SER_MAR18.PDF
R464 = RESISTOR: RES 220E 1/10W 5% 0402; Chkd/date: VASANTHA/291216; Crtd /date: GEETHA/260406; Custom_Duty: 15%; Customs_HS_Code: 85332119; Distributor_name: DIGIKEY; Distributor_part_number: P220JCT-ND; Footprint Path: Y:\MIS_DATABASE\Library\ALTIUM_TOOL\PCB_FOOTPRINTS\Altium_Footprint_Lib.PcbLib; Height: 0.40MM; Library Path: Y:\MIS_DATABASE\Library\ALTIUM_TOOL\SCHEMATICS_PARTS\MS_DISCRETE_Library.schlib; Mfr_name: PANASONIC-ECG; Mfr_part_number: ERJ-2GEJ221X; Mistral Part No: 110009030506-R; Package: 0402; Part_type: RESISTORS\FIXED; Project: RED EYE; RoHS: RoHS; Temperature: -55°C+155°C; Tolerance: 5%; Voltage: NA; Wattage: 1/10W; Weight: 0.8mg; Datasheet: Y:\MIS_DATABASE\DATASHEETS\RESISTORS\PAN-ERJSER_NOV17.PDF
U42 = TPD4E004_SON6: IC 4-CH ESD PROTECTION ARRAY FOR HIGH SPEED DATA INTERFACE SON6; Chkd/date: MANIRAJA/100320; Crtd /date: MUDDU/010310; Custom_Duty: 15%; Customs_HS_Code: 85423100; Distributor_name: DIGIKEY; Distributor_part_number: 296-23618-1-ND; Footprint Path: Y:\MIS_DATABASE\Library\ALTIUM_TOOL\PCB_FOOTPRINTS\Altium_Footprint_Lib.PcbLib; Height: 0.60MM; Library Path: Y:\MIS_DATABASE\Library\ALTIUM_TOOL\SCHEMATICS_PARTS\MS_MISCINTERFACE_Library.schlib; Mfr_name: TEXAS INSTRUMENTS; Mistral Part No: 141010020012-R; Package: SON6; Part_type: ICS\INTERFACE; Project: BUG_BASE-II; RoHS: RoHS; Temperature: -40°C+85°C; Tolerance: NA; Voltage: NA; Wattage: NA; Weight: 3.2mg; Datasheet: Y:\MIS_DATABASE\DATASHEETS\ICS\INTERFACE\TPD4E004-SER.PDF
U43 = TPS73501DRVR_SON6: IC 500mA LOW DROPOUT REGULATOR SON6; Chkd/date: VASANTHA/280915; Crtd /date: NAVEED/011014; Custom_Duty: 15%; Customs_HS_Code: 85423100; Distributor_name: DIGIKEY; Distributor_part_number: TPS73533DRVR-ND; Height: 0.80MM; Mfr_name: TEXAS INSTRUMENTS; Mistral Part No: 142014100001-R; Package: SON6; Part_type: ICS\POWER\VOLTAGE REGULATOR; Project: BLUETOOTH_WATCH; RoHS: RoHS; Temperature: -40°C+125°C; Tolerance: NA; Voltage: NA; Wattage: NA; Weight: NA; Datasheet: Y:\MIS_DATABASE\DATASHEETS\ICS\POWER\TPS735.PDF
U82 U84 U89 = SN74AVC4T245RSV_UQFN16: IC 2-BIT BUS TRANSCEIVER WITH CONFIGURABLE VOLTAGE TRANSLATION AND 3 STATE O/P UQFN16; Chkd/date: MANIRAJA/040520; Crtd /date: BAVISH/190411; Custom_Duty: 15%; Customs_HS_Code: 85423100; Distributor_name: DIGIKEY; Distributor_part_number: 296-24366-1-ND; Footprint Path: Y:\MIS_DATABASE\Library\ALTIUM_TOOL\PCB_FOOTPRINTS\Altium_Footprint_Lib.PcbLib; Height: 0.55MM; Library Path: Y:\MIS_DATABASE\Library\ALTIUM_TOOL\SCHEMATICS_PARTS\MS_BUSDRIVERTRANSCEIVER_Library.schlib; Mfr_name: TEXAS INSTRUMENTS; Mistral Part No: 141011040011-R; Package: UQFN16; Part_type: ICS\DIGITAL\BUSTRANSCEIVER; Project: HMC; RoHS: RoHS; Temperature: -40°C+85°C; Tolerance: NA; Voltage: NA; Wattage: NA; Weight: 41mg; Datasheet: Y:\MIS_DATABASE\DATASHEETS\ICS\DIGITAL\BUSTRANSCEIVER\SN74AVC4T245-SER.PDF
U87 = FT4232H__LQFP64: IC HIGH SPEED QUAD USB UART LQFP64; Chkd/date: MANIRAJA/110917; Crtd /date: VIJAYALAKSHMI/120813; Custom_Duty: 15%; Customs_HS_Code: 85423100; Distributor_name: DIGIKEY; Distributor_part_number: 768-1026-1-ND; Footprint Path: Y:\MIS_DATABASE\Library\ALTIUM_TOOL\PCB_FOOTPRINTS\Altium_Footprint_Lib.PcbLib; Height: 1.60MM; Library Path: Y:\MIS_DATABASE\Library\ALTIUM_TOOL\SCHEMATICS_PARTS\MS_COMBINATIONAL_Library.schlib; Library Ref: FT4232H_LQFP64; Mfr_name: FTDI; Mfr_part_number: FT4232HL-REEL; Mistral Part No: 141013080006-R; Package: LQFP64; Part_type: ICS\DIGITAL\PERIPHERAL; Project: DM37XX; RoHS: RoHS; Temperature: -40°C+85°C; Tolerance: NA; Voltage: NA; Wattage: NA; Weight: 342.7mg; Datasheet: Y:\MIS_DATABASE\DATASHEETS\ICS\DIGITAL\PERIPHERAL\FT4232HX.PDF
U92 = 93LC46B_MSOP8: IC 1K MICROWIRE COMPATIBLE SERIAL EEPROM MSOP8; Chkd/date: MANIRAJA/150218; Crtd /date: ALVY/150218; Custom_Duty: 15%; Customs_HS_Code: 85423100; Distributor_name: DIGIKEY; Distributor_part_number: 93LC46B-I/MS-ND; Footprint Path: Y:\MIS_DATABASE\Library\ALTIUM_TOOL\PCB_FOOTPRINTS\Altium_Footprint_Lib.PcbLib; Height: 1.10MM; Library Path: Y:\MIS_DATABASE\Library\ALTIUM_TOOL\SCHEMATICS_PARTS\MS_MISCMEMORY_Library.schlib; Mfr_name: MICROCHIP; Mfr_part_number: 93LC46B-I/MS; Mistral Part No: 141118020002-R; Package: MSOP8; Part_type: ICS\DIGITAL\MEMORY; Project: TI_MAXIE_CPB; RoHS: RoHS; Temperature: -40°C+85°C; Tolerance: NA; Voltage: NA; Wattage: NA; Weight: 140mg; Datasheet: Y:\MIS_DATABASE\DATASHEETS\ICS\MEMORY\93LC46B.PDF
Y3 = CRY: CRY 12.000MHz 18pF SMD; Chkd/date: MANIRAJA/310818; Crtd /date: MANIRAJA/310818; Custom_Duty: 24%; Customs_HS_Code: 85439000; Distributor_name: DIGIKEY; Distributor_part_number: CTX1170CT-ND; Footprint Path: Y:\MIS_DATABASE\Library\ALTIUM_TOOL\PCB_FOOTPRINTS\Altium_Footprint_Lib.PcbLib; Height: 1.35MM; Library Path: Y:\MIS_DATABASE\Library\ALTIUM_TOOL\SCHEMATICS_PARTS\MS_DISCRETE_Library.schlib; Mfr_name: CTS; Mfr_part_number: 445I23D12M00000; Mistral Part No: 130018080040-R; Package: SMD; Part_type: CRYSTAL; Project: TI_MAXIE_CPB; RoHS: RoHS; Temperature: -40°C+85°C; Tolerance: NA; Voltage: NA; Wattage: NA; Weight: 50mg; Datasheet: Y:\MIS_DATABASE\DATASHEETS\MISC\CRY_OSC\445.PDF

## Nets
DGND: C148.2 C149.2 C150.2 C152.1 C154.1 C158.2 C159.1 C160.1 C170.2 C184.2 C407.1 C408.1 C409.1 C412.1 C413.1 C414.1 C416.1 C419.1 C420.1 C421.2 C422.1 C423.1 C424.1 C425.1 C427.2 C428.2 C429.1 C430.2 C433.2 C437.2 C438.2 C439.2 C440.1 C441.1 C442.1 C443.2 C445.1 C446.2 C451.2 D6.1 J26.5(GND) J37.6(VSS) J37.10 J37.11 J37.12(CD2) J37.13 J37.14 R175.1 R182.1 R397.1 R400.1 R405.2 R444.1 R445.1 U39.1(GND) U42.3(GND) U43.3(GND) U43.7(EP) U44.A6(VSS) U44.C4(VSSQ) U44.E7(VSS) U44.G5(VSS) U44.H10(VSS) U44.J5(VSS) U44.K8(VSS) U44.N2(VSSQ) U44.N5(VSSQ) U44.P4(VSSQ) U44.P6(VSSQ) U49.5(GND) U54.3(GND) U82.1(~{1OE}) U82.10(GND1) U82.11(GND2) U82.16(~{2OE}) U84.1(~{1OE}) U84.10(GND1) U84.11(GND2) U84.16(~{2OE}) U86.2(GND) U87.1(GND1) U87.5(GND2) U87.10(AGND) U87.11(GND3) U87.13(TEST) U87.15(GND4) U87.25(GND5) U87.35(GND6) U87.47(GND7) U87.51(GND8) U89.1(~{1OE}) U89.10(GND1) U89.11(GND2) U89.16(~{2OE}) U92.5(VSS) ; also on sheet 2 3 4 5 6 7 8 9 10 11 12 13 14 15 16 17 18 19 20 21 22 25 26 27 28 29 30 39 40
GNDUSB: C160.2 J26.SH1 J26.SH2 J26.SH3 J26.SH4 J26.SH5 J26.SH6 R182.2
VCC1V8: C170.1 C430.1 C443.1 R159.1 R160.1 R161.1 R162.1 R163.1 R164.1 R165.1 R166.1 R193.1 R456.1 R457.1 U44.C6(VCCQ) U44.M4(VCCQ) U44.N4(VCCQ) U44.P3(VCCQ) U44.P5(VCCQ) U54.5(VCC) ; also on sheet 11 12 13 14 15 18 21
VCC_1V8_FT4232: C419.2 C420.2 C440.2 C441.2 U87.12(VCORE) U87.37(VCORE) U87.49(VREGOUT) U87.64(VCORE)
VCC_3V3_FT4232: C158.1 C409.2 C412.2 C413.2 C414.2 C423.2 C424.2 C442.2 C445.2 FB23.2 FB24.2 LD21.2(ANODE) R186.2 R191.2 R463.2 U43.1(OUT) U82.2(VCCB) U84.2(VCCB) U87.20(VCCIO) U87.31(VCCIO) U87.42(VCCIO) U87.50(VREGIN) U87.56(VCCIO) U89.2(VCCB) U92.8(VCC)
VCC_3V3_SYS: C149.1 C150.1 C407.2 C408.2 C421.1 C429.2 C437.1 C438.1 R174.1 R196.2 R403.2 R406.2 R416.2 R426.1 R438.2 R481.1 U39.2(IN1) U39.3(IN2) U44.E6(VCC) U44.F5(VCC) U44.J10(VCC) U44.K9(VCC) U82.3(VCCA) U84.3(VCCA) U86.5(VCC) U89.3(VCCA) ; also on sheet 2 5 6 7 8 10 11 12 13 14 15 16 17 18 19 20 21 25 26 27 29 30 39 40
VDD_MMC1: C148.1 C184.1 FB9.1 U39.6(OUT1) U39.7(OUT2) U39.8(OUT3) ; also on sheet 3 4
VDD_MMC1_SD: C451.1 FB9.2 J37.4(VDD)
VDDIM: C427.1 C428.1 U44.C2(VDDIM)
VDDSHV_SD_IO: C446.1 R479.1 R480.1 R483.1 R484.1 R485.1 TP39.1(TP) U49.10(VCC) ; also on sheet 3 4
eMMC_RSTn: R193.2 U44.K5(RST_N) U54.4(Y)
FT4232_DO: R191.1 R192.2 U92.4(DO)
FT4232_EECLK: R186.1 U87.62(EECLK) U92.2(CLK)
FT4232_EECS: R463.1 U87.63(EECS) U92.1(CS)
FT4232_EEDATA: R192.1 U87.61(EEDATA) U92.3(DI)
FT4232_MCU_UART0_CTS_3V3: U82.12(2B2) U87.28(BDBUS2)
FT4232_MCU_UART0_RTS_3V3: U82.14(1B2) U87.29(BDBUS3)
FT4232_MCU_UART0_RX_3V3: U82.13(2B1) U87.26(BDBUS0)
FT4232_MCU_UART0_TX_3V3: U82.15(1B1) U87.27(BDBUS1)
FT4232_REF: R175.2 U87.6(REF)
FT4232_RESET: C416.2 R417.1 U87.14(~{RESET})
FT4232_UART0_CTS_3V3: U84.12(2B2) U87.18(ADBUS2)
FT4232_UART0_RTS_3V3: U84.14(1B2) U87.19(ADBUS3)
FT4232_UART0_RX_3V3: U84.13(2B1) U87.16(ADBUS0)
FT4232_UART0_TX_3V3: U84.15(1B1) U87.17(ADBUS1)
FT4232_UART1_RX_3V3: U87.38(CDBUS0) U89.13(2B1)
FT4232_UART1_TX_3V3: U87.39(CDBUS1) U89.15(1B1)
FT4232_UART3_RX_3V3: U87.48(DDBUS0) U89.12(2B2)
FT4232_UART3_TX_3V3: U87.52(DDBUS1) U89.14(1B2)
FT4232_USB_DM: J26.2(D-) U42.5(IO4) U87.7(DM)
FT4232_USB_DP: J26.3(D+) U42.4(IO3) U87.8(DP)
FT4232_USB_VBUS: C152.2 C154.2 D6.2 J26.1(VBUS) U42.6(VCC) U43.4(EN) U43.6(IN)
FT_PWREN#: R464.1 U87.60(~{PWREN})
GPIO_eMMC_RSTn: R196.1 U54.1(A) ; also on sheet 13
IO_EXP_INTn_SDIO: U23.C20(MMC1_SDWP) ; also on sheet 13
MCU_UART0_CTS_3V3: U82.9(2A2) ; also on sheet 12
MCU_UART0_RTS_3V3: U82.7(1A2) ; also on sheet 12
MCU_UART0_RX_3V3: U82.8(2A1) ; also on sheet 12
MCU_UART0_TX_3V3: U82.6(1A1) ; also on sheet 12
MMC0_CALPAD: R405.1 U23.F18(MMC0_CALPAD)
MMC0_CLK: R404.1 R456.2 U44.M6(CLK)
MMC0_DS: R444.2 R446.2 U44.H5(DS)
MMC0_VCTRL_TP: TP74.1(TP) U23.F17(MMC0_VCTRL_TP)
MMC1_CLK: J37.5(CLK) R389.1 U49.1(IO1)
MMC1_CLK_R: R389.2 U23.L20(MMC1_CLK)
MMC1_CMD: J37.3(CMD) R485.2 U23.J19(MMC1_CMD) U49.2(IO2)
MMC1_D0: J37.7(DAT0) R479.2 U23.K21(MMC1_DAT0) U49.8(IO6)
MMC1_D1: J37.8(DAT1) R480.2 U23.L21(MMC1_DAT1) U49.7(IO5)
MMC1_D2: J37.1(DAT2) R483.2 U23.K19(MMC1_DAT2) U49.6(IO4)
MMC1_D3: J37.2(CD/DAT3) R484.2 U23.K18(MMC1_DAT3) U49.3(IO3)
MMC1_SD_EN: R416.1 U86.1(A) ; also on sheet 13
MMC1_SD_LS_EN: R426.2 U39.4(EN) U86.4(Y)
MMC1_SDCD: J37.9(CD1) R481.2 U23.D19(MMC1_SDCD)
PORz_OUT: U86.6(C) ; also on sheet 2 12 29 39 40
RESETSTATz: U54.2(B) U86.3(B) ; also on sheet 5 12 13 21 29
SOC_MAIN_UART0_CTS_3V3: U84.9(2A2) ; also on sheet 6
SOC_MAIN_UART0_RTS_3V3: U84.7(1A2) ; also on sheet 6
SOC_MAIN_UART0_RX_3V3: U84.8(2A1) ; also on sheet 6
SOC_MAIN_UART0_TX_3V3: U84.6(1A1) ; also on sheet 6
SOC_MAIN_UART1_RX_3V3: U89.8(2A1) ; also on sheet 6
SOC_MAIN_UART1_TX_3V3: U89.6(1A1) ; also on sheet 6
SOC_MAIN_UART3_RX_3V3: U89.9(2A2) ; also on sheet 6
SOC_MAIN_UART3_TX_3V3: U89.7(1A2) ; also on sheet 6
SoC_MMC0_CLK: R404.2 U23.G18(MMC0_CLK)
SoC_MMC0_CMD: R457.2 U23.J21(MMC0_CMD) U44.M5(CMD)
SoC_MMC0_DAT0: R161.2 U23.K20(MMC0_DAT0) U44.A3(DAT0)
SoC_MMC0_DAT1: R163.2 U23.J20(MMC0_DAT1) U44.A4(DAT1)
SoC_MMC0_DAT2: R165.2 U23.J18(MMC0_DAT2) U44.A5(DAT2)
SoC_MMC0_DAT3: R159.2 U23.J17(MMC0_DAT3) U44.B2(DAT3)
SoC_MMC0_DAT4: R160.2 U23.H17(MMC0_DAT4) U44.B3(DAT4)
SoC_MMC0_DAT5: R162.2 U23.H19(MMC0_DAT5) U44.B4(DAT5)
SoC_MMC0_DAT6: R164.2 U23.H18(MMC0_DAT6) U44.B5(DAT6)
SoC_MMC0_DAT7: R166.2 U23.G17(MMC0_DAT7) U44.B6(DAT7)
SoC_MMC0_DS: R446.1 U23.G19(MMC0_DS)
VPHY_3V3_FT4232: C425.2 FB24.1 U87.4(VPHY)
VPLL_3V3_FT4232: C422.2 FB23.1 R417.2 U87.9(VPLL)
N15507744: C159.2 U43.2(NR/FB)
N16814557: R445.2 U89.5(2DIR)
N16814563: R438.1 U89.4(1DIR)
N16814605: R400.2 U84.5(2DIR)
N16814611: R406.1 U84.4(1DIR)
N16814651: R397.2 U82.5(2DIR)
N16814659: R403.1 U82.4(1DIR)
N18977129: C433.1 U87.3(OSCO) Y3.2
N18977189: C439.1 U87.2(OSCI) Y3.1
N22464359: R174.2 U39.5(~{OC})
N26881621: LD21.1(CATHODE) R464.2

Not connected (* = marked no-connect by the designer): J26 4(ID)*; U42 1(IO1)* 2(IO2)*; U43 5(NC)*; U44 A1(NC1)* A2(NC2)* A7(RFU1)* A8(NC3)* A9(NC4)* A10(NC5)* A11(NC6)* A12(NC7)* A13(NC8)* A14(NC9)* B1(NC10)* B7(NC11)* B8(NC12)* B9(NC13)* B10(NC14)* B11(NC15)* B12(NC16)* B13(NC17)* B14(NC18)* C1(NC19)* C3(NC20)* C5(NC21)* C7(NC22)* C8(NC23)* C9(NC24)* C10(NC25)* C11(NC26)* C12(NC27)* C13(NC28)* C14(NC29)* D1(NC30)* D2(NC31)* D3(NC32)* D4(NC33)* D12(NC34)* D13(NC35)* D14(NC36)* E1(NC37)* E2(NC38)* E3(NC39)* E5(RFU2)* E8(VSF1)* E9(VSF2)* E10(VSF3)* E12(NC40)* E13(NC41)* E14(NC42)* F1(NC43)* F2(NC44)* F3(NC45)* F10(VSF4)* F12(NC46)* F13(NC47)* F14(NC48)* G1(NC49)* G2(NC50)* G3(NC51)* G10(VSF5)* G12(NC52)* G13(NC53)* G14(NC54)* H1(NC55)* H2(NC56)* H3(NC57)* H12(NC58)* H13(NC59)* H14(NC60)* J1(NC61)* J2(NC62)* J3(NC63)* J12(NC64)* J13(NC65)* J14(NC66)* K1(NC67)* K2(NC68)* K3(NC69)* K6(RFU3)* K7(RFU4)* K10(VSF6)* K12(NC70)* K13(NC71)* K14(NC72)* L1(NC73)* L2(NC74)* L3(NC75)* L12(NC76)* L13(NC77)* L14(NC78)* M1(NC79)* M2(NC80)* M3(NC81)* M7(NC82)* M8(NC83)* M9(NC84)* M10(NC85)* M11(NC86)* M12(NC87)* M13(NC88)* M14(NC89)* N1(NC90)* N3(NC91)* N6(NC92)* N7(NC93)* N8(NC94)* N9(NC95)* N10(NC96)* N11(NC97)* N12(NC98)* N13(NC99)* N14(NC100)* P1(NC101)* P2(NC102)* P7(NC103)* P8(NC104)* P9(NC105)* P10(VSF7)* P11(NC106)* P12(NC107)* P13(NC108)* P14(NC109)*; U49 4(NC1)* 9(NC2)*; U87 21(ADBUS4)* 22(ADBUS5)* 23(ADBUS6)* 24(ADBUS7)* 30(BDBUS4)* 32(BDBUS5)* 33(BDBUS6)* 34(BDBUS7)* 36(~{SUSPEND}) 40(CDBUS2)* 41(CDBUS3)* 43(CDBUS4)* 44(CDBUS5)* 45(CDBUS6)* 46(CDBUS7)* 53(DDBUS2)* 54(DDBUS3)* 55(DDBUS4)* 57(DDBUS5)* 58(DDBUS6)* 59(DDBUS7)*; U92 6(NC1)* 7(NC2)*

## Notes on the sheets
sheet 23
- FT4232 UART
- USB Micro B
- FT4232: 5V to 3.3V@500mA LDO
- FT4232 LEVEL TRANSLATOR
- Off Page Connections
- EEPROM
sheet 24
- eMMC FLASH
- eMMC FLASH RESET
- SD CARD INTERFACE
- Off Page Connections
- From &
  To IO Expander
